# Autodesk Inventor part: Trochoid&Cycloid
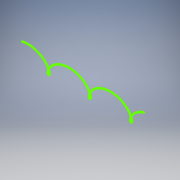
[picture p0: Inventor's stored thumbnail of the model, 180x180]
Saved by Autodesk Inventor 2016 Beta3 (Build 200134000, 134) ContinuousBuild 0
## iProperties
Created: 2008-02
Part Number: Trochoid&Cycloid
Document SubType Name: Modeling
Designer: Autodesk, Inc.
Density: 1 g/cm^3
Material: Generic
Appearance: Default
Author: Autodesk, Inc.
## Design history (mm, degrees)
sketch "Sketch1"
  geometry: 300 further points
  constraints: 300 other
